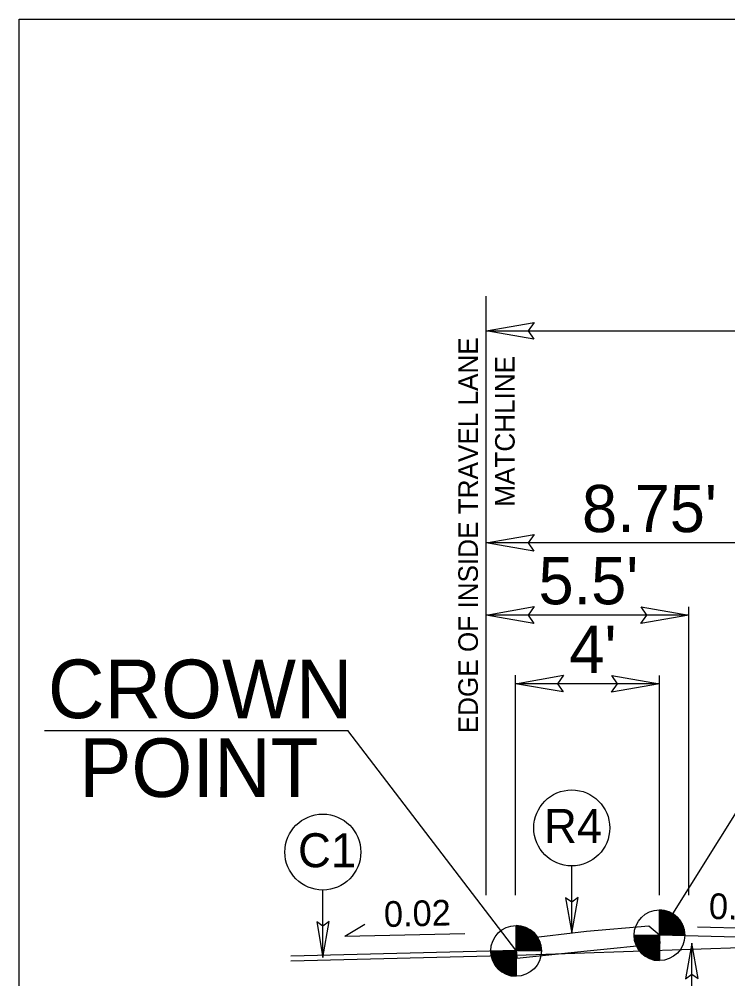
# Model space of a CAD drawing. Extents: x 3025871 to 3026431, y 707165 to 707825.
# Drawn here: x 3026334.09 to 3026352.23, y 707468.77 to 707493.34 of the extents above; entities that cross this region are included whole.
import ezdxf

# ---------------------------------------------------------------- set-up
doc = ezdxf.new("R2010")
doc.units = 0
for name, color, linetype in [('Prop Dimension', 7, 'Continuous'), ('Prop Drainage Structure Junction Box with Slab Lid CELL', 7, 'Continuous'), ('Prop Drainage Structure Junction Box with Slab Lid TB 840 34 CELL', 7, 'Continuous'), ('Prop Drainage Structure Plot Symbol 20 Scale', 7, 'Continuous'), ('Prop Pavement Schedule Description CELL', 7, 'Continuous'), ('Sheet Sticker Incomplete CELL', 7, 'Continuous'), ('Typical Arrow Superelevation CELL', 7, 'Continuous'), ('Typical Grade Point Symbol CELL', 7, 'Continuous'), ('Typical Shoulder Slope CELL', 7, 'Continuous'), ('Typical Text Centerline CELL', 7, 'Continuous')]:
    doc.layers.add(name, color=color, linetype=linetype)

msp = doc.modelspace()

# ---------------------------------------------------------------- linework, layer by layer
at = {"layer": 'Prop Dimension'}
for p, q in [((3026348.612, 707469.983), (3026347.033, 707469.789)), ((3026350.209, 707470.113), (3026348.612, 707469.983)), ((3026350.484, 707469.884), (3026350.209, 707470.113)), ((3026347.033, 707469.789), (3026346.811, 707469.51)), ((3026350.505, 707469.675), (3026350.484, 707469.884)), ((3026346.811, 707469.51), (3026346.832, 707469.301)), ((3026346.832, 707469.301), (3026348.636, 707469.485)), ((3026348.636, 707469.485), (3026350.505, 707469.675))]:
    msp.add_line(p, q, dxfattribs=at)
at = {"layer": 'Prop Drainage Structure Junction Box with Slab Lid CELL'}
for p, q in [((3026350.484, 707469.884), (3026350.484, 707470.533)), ((3026346.813, 707469.484), (3026346.814, 707470.133)), ((3026349.835, 707469.884), (3026350.484, 707469.884)), ((3026350.482, 707469.235), (3026350.484, 707469.884)), ((3026350.484, 707469.884), (3026350.482, 707469.235)), ((3026351.133, 707469.884), (3026350.484, 707469.884)), ((3026346.164, 707469.484), (3026346.813, 707469.484)), ((3026346.812, 707468.835), (3026346.813, 707469.484)), ((3026346.813, 707469.484), (3026346.812, 707468.835)), ((3026347.463, 707469.484), (3026346.813, 707469.484))]:
    msp.add_line(p, q, dxfattribs=at)
for points in [[(3026350.49, 707470.533), (3026350.49, 707470.533), (3026350.49, 707469.884)], [(3026350.503, 707470.533), (3026350.503, 707469.884)], [(3026350.516, 707470.532), (3026350.516, 707469.884)], [(3026350.529, 707470.532), (3026350.529, 707469.884)], [(3026350.542, 707470.531), (3026350.542, 707469.884)], [(3026350.555, 707470.529), (3026350.555, 707469.884)], [(3026350.568, 707470.528), (3026350.568, 707469.884)], [(3026350.581, 707470.526), (3026350.581, 707469.884)], [(3026350.594, 707470.525), (3026350.594, 707469.884)], [(3026350.607, 707470.522), (3026350.607, 707469.884)], [(3026350.62, 707470.519), (3026350.62, 707469.884)], [(3026350.633, 707470.516), (3026350.633, 707469.884)], [(3026350.646, 707470.513), (3026350.646, 707469.884)], [(3026350.659, 707470.509), (3026350.659, 707469.884)], [(3026350.672, 707470.506), (3026350.672, 707469.884)], [(3026350.685, 707470.502), (3026350.685, 707469.884)], [(3026350.698, 707470.497), (3026350.698, 707469.884)], [(3026350.711, 707470.493), (3026350.711, 707469.884)], [(3026350.724, 707470.487), (3026350.724, 707469.884)], [(3026350.737, 707470.482), (3026350.737, 707469.884)], [(3026350.75, 707470.476), (3026350.75, 707469.884)], [(3026350.763, 707470.47), (3026350.763, 707469.884)], [(3026350.776, 707470.464), (3026350.776, 707469.884)], [(3026350.789, 707470.457), (3026350.788, 707469.884)], [(3026350.802, 707470.45), (3026350.801, 707469.884)], [(3026350.815, 707470.443), (3026350.814, 707469.884)], [(3026350.828, 707470.435), (3026350.827, 707469.884)], [(3026350.841, 707470.427), (3026350.84, 707469.884)], [(3026350.854, 707470.418), (3026350.853, 707469.884)], [(3026350.867, 707470.408), (3026350.866, 707469.884)], [(3026350.88, 707470.399), (3026350.879, 707469.884)], [(3026350.893, 707470.389), (3026350.892, 707469.884)], [(3026350.906, 707470.378), (3026350.905, 707469.884)], [(3026350.918, 707470.366), (3026350.918, 707469.884)], [(3026350.931, 707470.354), (3026350.931, 707469.884)], [(3026350.944, 707470.341), (3026350.944, 707469.884)], [(3026350.957, 707470.328), (3026350.957, 707469.884)], [(3026350.97, 707470.314), (3026350.97, 707469.884)], [(3026350.983, 707470.298), (3026350.983, 707469.884)], [(3026350.996, 707470.282), (3026350.996, 707469.884)], [(3026351.009, 707470.265), (3026351.009, 707469.884)], [(3026351.022, 707470.246), (3026351.022, 707469.884)], [(3026351.035, 707470.226), (3026351.035, 707469.884)], [(3026351.048, 707470.204), (3026351.048, 707469.884)], [(3026346.819, 707470.133), (3026346.819, 707470.133), (3026346.819, 707469.484)], [(3026346.832, 707470.133), (3026346.832, 707469.484)], [(3026346.845, 707470.132), (3026346.845, 707469.484)], [(3026346.858, 707470.132), (3026346.858, 707469.484)], [(3026346.871, 707470.13), (3026346.871, 707469.484)], [(3026346.884, 707470.129), (3026346.884, 707469.484)], [(3026346.897, 707470.128), (3026346.897, 707469.484)], [(3026346.91, 707470.126), (3026346.91, 707469.484)], [(3026346.923, 707470.125), (3026346.923, 707469.484)], [(3026346.936, 707470.122), (3026346.936, 707469.484)], [(3026346.949, 707470.119), (3026346.949, 707469.484)], [(3026346.962, 707470.116), (3026346.962, 707469.484)], [(3026346.975, 707470.113), (3026346.975, 707469.484)], [(3026346.988, 707470.109), (3026346.988, 707469.484)], [(3026347.001, 707470.106), (3026347.001, 707469.484)], [(3026347.014, 707470.101), (3026347.014, 707469.484)], [(3026347.027, 707470.097), (3026347.027, 707469.484)], [(3026347.04, 707470.093), (3026347.04, 707469.484)], [(3026347.053, 707470.087), (3026347.053, 707469.484)], [(3026347.066, 707470.081), (3026347.066, 707469.484)], [(3026347.079, 707470.075), (3026347.079, 707469.484)], [(3026347.092, 707470.07), (3026347.092, 707469.484)], [(3026347.105, 707470.064), (3026347.105, 707469.484)], [(3026347.118, 707470.057), (3026347.118, 707469.484)], [(3026347.131, 707470.05), (3026347.131, 707469.484)], [(3026347.144, 707470.042), (3026347.144, 707469.484)], [(3026347.157, 707470.035), (3026347.157, 707469.484)], [(3026347.17, 707470.026), (3026347.17, 707469.484)], [(3026347.183, 707470.018), (3026347.183, 707469.484)], [(3026347.196, 707470.008), (3026347.196, 707469.484)], [(3026347.209, 707469.999), (3026347.209, 707469.484)], [(3026347.222, 707469.989), (3026347.222, 707469.484)], [(3026347.235, 707469.977), (3026347.235, 707469.484)], [(3026347.248, 707469.966), (3026347.248, 707469.484)], [(3026347.261, 707469.954), (3026347.261, 707469.484)], [(3026347.274, 707469.941), (3026347.274, 707469.484)], [(3026351.061, 707470.181), (3026351.061, 707469.884)], [(3026351.074, 707470.154), (3026351.074, 707469.884)], [(3026351.087, 707470.124), (3026351.087, 707469.884)], [(3026351.1, 707470.087), (3026351.1, 707469.884)], [(3026351.113, 707470.043), (3026351.113, 707469.884)], [(3026351.126, 707469.976), (3026351.126, 707469.884)], [(3026347.287, 707469.928), (3026347.287, 707469.484)], [(3026347.3, 707469.914), (3026347.3, 707469.484)], [(3026347.313, 707469.898), (3026347.313, 707469.484)], [(3026347.326, 707469.882), (3026347.326, 707469.484)], [(3026347.339, 707469.865), (3026347.339, 707469.484)], [(3026347.352, 707469.846), (3026347.352, 707469.484)], [(3026347.365, 707469.826), (3026347.365, 707469.484)], [(3026347.378, 707469.804), (3026347.378, 707469.484)], [(3026347.391, 707469.781), (3026347.391, 707469.484)], [(3026347.404, 707469.754), (3026347.404, 707469.484)], [(3026347.417, 707469.723), (3026347.416, 707469.484)], [(3026349.838, 707469.884), (3026349.838, 707469.814)], [(3026349.851, 707469.884), (3026349.85, 707469.737)], [(3026349.864, 707469.884), (3026349.863, 707469.691)], [(3026349.877, 707469.884), (3026349.876, 707469.652)], [(3026349.89, 707469.884), (3026349.889, 707469.622)], [(3026349.903, 707469.884), (3026349.902, 707469.594)], [(3026349.916, 707469.884), (3026349.915, 707469.57)], [(3026349.929, 707469.884), (3026349.928, 707469.547)], [(3026349.942, 707469.884), (3026349.941, 707469.527)], [(3026349.954, 707469.884), (3026349.954, 707469.508)], [(3026349.967, 707469.884), (3026349.967, 707469.49)], [(3026349.98, 707469.884), (3026349.98, 707469.475)], [(3026349.993, 707469.884), (3026349.993, 707469.459)], [(3026350.006, 707469.884), (3026350.006, 707469.444)], [(3026350.019, 707469.884), (3026350.019, 707469.43)], [(3026350.032, 707469.884), (3026350.032, 707469.417)], [(3026350.045, 707469.884), (3026350.045, 707469.405)], [(3026350.058, 707469.884), (3026350.058, 707469.394)], [(3026350.071, 707469.884), (3026350.071, 707469.382)], [(3026350.084, 707469.884), (3026350.084, 707469.372)], [(3026350.097, 707469.884), (3026350.097, 707469.362)], [(3026350.11, 707469.884), (3026350.11, 707469.353)], [(3026350.123, 707469.884), (3026350.123, 707469.345)], [(3026350.136, 707469.884), (3026350.136, 707469.336)], [(3026350.149, 707469.884), (3026350.149, 707469.327)], [(3026350.162, 707469.884), (3026350.162, 707469.32)], [(3026350.175, 707469.884), (3026350.175, 707469.313)], [(3026350.188, 707469.884), (3026350.188, 707469.306)], [(3026350.201, 707469.884), (3026350.201, 707469.3)], [(3026350.214, 707469.884), (3026350.214, 707469.294)], [(3026350.227, 707469.884), (3026350.227, 707469.288)], [(3026350.24, 707469.884), (3026350.24, 707469.283)], [(3026350.253, 707469.884), (3026350.253, 707469.277)], [(3026350.266, 707469.884), (3026350.266, 707469.272)], [(3026350.279, 707469.884), (3026350.279, 707469.268)], [(3026350.292, 707469.884), (3026350.292, 707469.264)], [(3026350.305, 707469.884), (3026350.305, 707469.261)], [(3026350.318, 707469.884), (3026350.318, 707469.257)], [(3026350.331, 707469.884), (3026350.331, 707469.254)], [(3026350.344, 707469.884), (3026350.344, 707469.251)], [(3026350.357, 707469.884), (3026350.357, 707469.248)], [(3026350.37, 707469.884), (3026350.37, 707469.245)], [(3026350.383, 707469.884), (3026350.383, 707469.244)], [(3026350.396, 707469.884), (3026350.396, 707469.241)], [(3026350.409, 707469.884), (3026350.409, 707469.239)], [(3026350.422, 707469.884), (3026350.422, 707469.238)], [(3026350.435, 707469.884), (3026350.435, 707469.236)], [(3026350.448, 707469.884), (3026350.448, 707469.236)], [(3026350.461, 707469.884), (3026350.461, 707469.235)], [(3026350.474, 707469.884), (3026350.474, 707469.235), (3026350.474, 707469.235)], [(3026346.167, 707469.484), (3026346.167, 707469.413)], [(3026346.18, 707469.484), (3026346.18, 707469.337)], [(3026346.193, 707469.484), (3026346.193, 707469.291)], [(3026346.206, 707469.484), (3026346.206, 707469.252)], [(3026346.219, 707469.484), (3026346.219, 707469.222)], [(3026346.232, 707469.484), (3026346.232, 707469.194)], [(3026346.245, 707469.484), (3026346.245, 707469.17)], [(3026346.258, 707469.484), (3026346.258, 707469.147)], [(3026346.271, 707469.484), (3026346.271, 707469.126)], [(3026346.284, 707469.484), (3026346.284, 707469.108)], [(3026346.297, 707469.484), (3026346.297, 707469.09)], [(3026346.31, 707469.484), (3026346.31, 707469.074)], [(3026346.323, 707469.484), (3026346.323, 707469.059)], [(3026346.336, 707469.484), (3026346.336, 707469.044)], [(3026346.349, 707469.484), (3026346.349, 707469.03)], [(3026346.362, 707469.484), (3026346.362, 707469.017)], [(3026346.375, 707469.484), (3026346.375, 707469.005)], [(3026346.388, 707469.484), (3026346.388, 707468.994)], [(3026346.401, 707469.484), (3026346.401, 707468.982)], [(3026346.414, 707469.484), (3026346.414, 707468.972)], [(3026346.427, 707469.484), (3026346.427, 707468.962)], [(3026346.44, 707469.484), (3026346.439, 707468.953)], [(3026346.453, 707469.484), (3026346.452, 707468.944)], [(3026346.466, 707469.484), (3026346.465, 707468.936)], [(3026346.479, 707469.484), (3026346.478, 707468.927)], [(3026346.492, 707469.484), (3026346.491, 707468.92)], [(3026346.505, 707469.484), (3026346.504, 707468.913)], [(3026346.518, 707469.484), (3026346.517, 707468.905)], [(3026346.531, 707469.484), (3026346.53, 707468.9)], [(3026346.544, 707469.484), (3026346.543, 707468.894)], [(3026346.557, 707469.484), (3026346.556, 707468.888)], [(3026346.569, 707469.484), (3026346.569, 707468.882)], [(3026346.582, 707469.484), (3026346.582, 707468.877)], [(3026346.595, 707469.484), (3026346.595, 707468.872)], [(3026346.608, 707469.484), (3026346.608, 707468.868)], [(3026346.621, 707469.484), (3026346.621, 707468.864)], [(3026346.634, 707469.484), (3026346.634, 707468.861)], [(3026346.647, 707469.484), (3026346.647, 707468.856)], [(3026346.66, 707469.484), (3026346.66, 707468.854)], [(3026346.673, 707469.484), (3026346.673, 707468.851)], [(3026346.686, 707469.484), (3026346.686, 707468.848)], [(3026346.699, 707469.484), (3026346.699, 707468.845)], [(3026346.712, 707469.484), (3026346.712, 707468.843)], [(3026346.725, 707469.484), (3026346.725, 707468.841)], [(3026346.738, 707469.484), (3026346.738, 707468.839)], [(3026346.751, 707469.484), (3026346.751, 707468.838)], [(3026346.764, 707469.484), (3026346.764, 707468.836)], [(3026346.777, 707469.484), (3026346.777, 707468.836)], [(3026346.79, 707469.484), (3026346.79, 707468.835)], [(3026346.803, 707469.484), (3026346.803, 707468.835), (3026346.803, 707468.835)], [(3026347.43, 707469.687), (3026347.429, 707469.484)], [(3026347.443, 707469.642), (3026347.442, 707469.484)], [(3026347.456, 707469.576), (3026347.455, 707469.484)]]:
    msp.add_lwpolyline(points, dxfattribs=at)
for centre in [(3026350.483, 707469.884), (3026346.813, 707469.484)]:
    msp.add_circle(centre, 0.649, dxfattribs=at)
for centre, start, end in [((3026350.483, 707469.884), 359.9709, 89.9709), ((3026346.813, 707469.484), 359.9709, 89.9709), ((3026350.483, 707469.884), 179.9709, 269.9709), ((3026346.813, 707469.484), 179.9709, 269.9709)]:
    msp.add_arc(centre, 0.649, start, end, dxfattribs=at)
at = {"layer": 'Prop Drainage Structure Junction Box with Slab Lid TB 840 34 CELL'}
for p, q in [((3026346.046, 707470.908), (3026346.046, 707486.254)), ((3026346.046, 707485.361), (3026363.546, 707485.361)), ((3026363.471, 707479.931), (3026346.046, 707479.931)), ((3026351.239, 707470.908), (3026351.239, 707478.293)), ((3026351.239, 707478.082), (3026346.046, 707478.082)), ((3026346.796, 707470.908), (3026346.796, 707476.543)), ((3026350.489, 707470.908), (3026350.489, 707476.536)), ((3026350.489, 707476.325), (3026346.796, 707476.325))]:
    msp.add_line(p, q, dxfattribs=at)
msp.add_lwpolyline([(3026370.091, 707463.345), (3026334.091, 707463.345), (3026334.091, 707493.345), (3026370.091, 707493.345)], close=True, dxfattribs=at)
at = {"layer": 'Prop Drainage Structure Plot Symbol 20 Scale'}
for p, q in [((3026350.484, 707469.884), (3026355.212, 707477.464)), ((3026346.804, 707469.502), (3026342.501, 707475.128))]:
    msp.add_line(p, q, dxfattribs=at)
at = {"layer": 'Prop Pavement Schedule Description CELL'}
for p, q in [((3026368.546, 707469.433), (3026350.484, 707469.884)), ((3026341.046, 707469.358), (3026346.812, 707469.502)), ((3026346.824, 707469.377), (3026354.796, 707469.651)), ((3026341.046, 707469.233), (3026346.824, 707469.377))]:
    msp.add_line(p, q, dxfattribs=at)
at = {"layer": 'Sheet Sticker Incomplete CELL'}
for p, q in [((3026342.43, 707469.857), (3026342.944, 707470.171)), ((3026354.521, 707470.016), (3026351.454, 707470.092)), ((3026342.43, 707469.857), (3026345.497, 707469.933))]:
    msp.add_line(p, q, dxfattribs=at)
at = {"layer": 'Typical Grade Point Symbol CELL'}
for p, q in [((3026348.239, 707469.937), (3026348.238, 707471.661)), ((3026341.866, 707469.318), (3026341.865, 707471.042)), ((3026351.315, 707468.062), (3026351.314, 707469.685))]:
    msp.add_line(p, q, dxfattribs=at)
for centre in [(3026348.238, 707472.633), (3026341.865, 707472.014)]:
    msp.add_circle(centre, 0.972, dxfattribs=at)
at = {"layer": 'Typical Shoulder Slope CELL'}
msp.add_line((3026334.741, 707475.131), (3026342.501, 707475.128), dxfattribs=at)
at = {"layer": 'Typical Text Centerline CELL'}
for points in [[(3026347.271, 707485.15), (3026346.046, 707485.361), (3026347.278, 707485.579), (3026347.122, 707485.361)], [(3026347.271, 707479.72), (3026346.046, 707479.931), (3026347.278, 707480.148), (3026347.122, 707479.931)], [(3026347.271, 707477.871), (3026346.046, 707478.082), (3026347.278, 707478.3), (3026347.122, 707478.082)], [(3026350.014, 707478.293), (3026351.239, 707478.082), (3026350.007, 707477.865), (3026350.164, 707478.082)], [(3026348.021, 707476.114), (3026346.796, 707476.325), (3026348.028, 707476.543), (3026347.872, 707476.325)], [(3026349.263, 707476.536), (3026350.489, 707476.325), (3026349.257, 707476.107), (3026349.413, 707476.325)], [(3026348.082, 707470.846), (3026348.239, 707469.937), (3026348.4, 707470.852), (3026348.239, 707470.735)], [(3026341.709, 707470.227), (3026341.866, 707469.318), (3026342.027, 707470.232), (3026341.866, 707470.116)], [(3026351.472, 707468.776), (3026351.314, 707469.685), (3026351.153, 707468.77), (3026351.315, 707468.887)]]:
    msp.add_lwpolyline(points, close=True, dxfattribs=at)

# ---------------------------------------------------------------- texts
at = {"layer": 'Prop Drainage Structure Junction Box with Slab Lid TB 840 34 CELL'}
for s, p in [("8.75'", (3026348.5, 707480.208)), ("5.5'", (3026347.387, 707478.36)), ("4'", (3026348.177, 707476.603))]:
    msp.add_text(s, height=1.2089, dxfattribs=at).set_placement(p)
at = {"layer": 'Sheet Sticker Incomplete CELL'}
for s, height, rotation, p in [('EDGE OF INSIDE TRAVEL LANE', 0.5, 90, (3026345.835, 707475.056)), ('MATCHLINE', 0.5, 90, (3026346.776, 707480.858)), ('0.02', 0.6583, 358.5679, (3026351.743, 707470.303)), ('0.02', 0.6583, 1.4321, (3026343.437, 707470.094))]:
    msp.add_text(s, height=height, rotation=rotation, dxfattribs=at).set_placement(p)
at = {"layer": 'Typical Arrow Superelevation CELL'}
for s, p in [('R4', (3026347.529, 707472.25)), ('C1', (3026341.23, 707471.626))]:
    msp.add_text(s, height=0.87, dxfattribs=at).set_placement(p)
at = {"layer": 'Typical Shoulder Slope CELL'}
for s, p in [('CROWN', (3026334.826, 707475.444)), ('POINT', (3026335.625, 707473.427))]:
    msp.add_text(s, height=1.5, rotation=359.9804, dxfattribs=at).set_placement(p)

doc.saveas('drawing.dxf')
